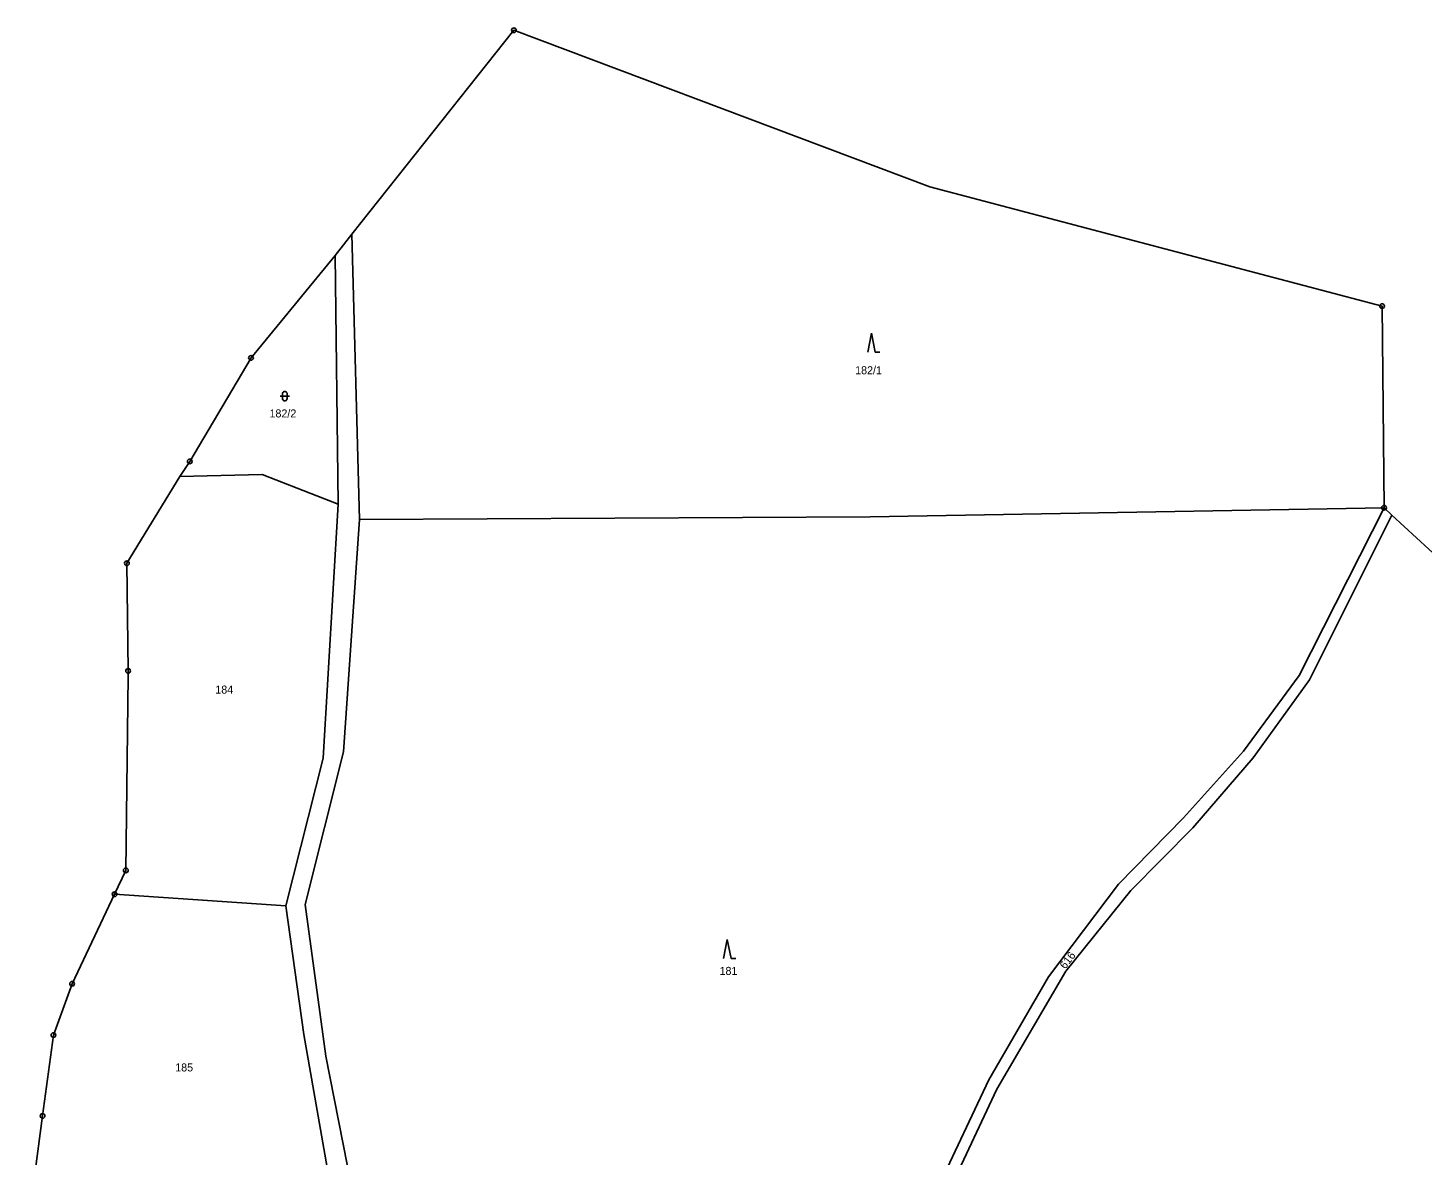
# Model space of a CAD drawing. Extents: x -794421 to -792735, y -1117671 to -1115559.
# Drawn here: x -793544 to -793247.9, y -1115798.8 to -1115559.5 of the extents above; entities that cross this region are included whole.
import ezdxf

# ---------------------------------------------------------------- set-up
doc = ezdxf.new("R2010")
doc.units = 0
for name, color, linetype in [('Vrstva 1', 7, 'Continuous'), ('Vrstva 14', 7, 'Continuous'), ('Vrstva 23', 7, 'Continuous'), ('Vrstva 28', 7, 'Continuous'), ('Vrstva 3', 7, 'Continuous')]:
    doc.layers.add(name, color=color, linetype=linetype)

msp = doc.modelspace()

# ---------------------------------------------------------------- linework, layer by layer
at = {"layer": 'Vrstva 1'}
for p, q in [((-793475.17, -1115603.32), (-793473.53, -1115663.84)), ((-793478.72, -1115607.79), (-793478.08, -1115660.64)), ((-793511.69, -1115654.77), (-793494.18, -1115654.33)), ((-793494.18, -1115654.33), (-793478.08, -1115660.64)), ((-793478.08, -1115660.64), (-793481.27, -1115714.55)), ((-793365.11, -1115663.31), (-793255.97, -1115661.39)), ((-793255.97, -1115661.39), (-793273.99, -1115696.97)), ((-793473.53, -1115663.84), (-793476.92, -1115713.19)), ((-793473.53, -1115663.84), (-793365.11, -1115663.31)), ((-793271.79, -1115697.9), (-793254.28, -1115662.95)), ((-793273.99, -1115696.97), (-793285.84, -1115713.04)), ((-793271.79, -1115697.9), (-793283.72, -1115714.46)), ((-793481.27, -1115714.55), (-793489.16, -1115745.93)), ((-793476.92, -1115713.19), (-793485.04, -1115745.64)), ((-793285.84, -1115713.04), (-793298.55, -1115727.22)), ((-793283.72, -1115714.46), (-793296.6, -1115729.31)), ((-793298.55, -1115727.22), (-793312.33, -1115741.27)), ((-793296.6, -1115729.31), (-793309.74, -1115742.61)), ((-793312.33, -1115741.27), (-793327.22, -1115760.95)), ((-793525.55, -1115743.43), (-793489.16, -1115745.93)), ((-793309.74, -1115742.61), (-793323.54, -1115759.78)), ((-793489.16, -1115745.93), (-793485.36, -1115773.22)), ((-793485.04, -1115745.64), (-793480.65, -1115777.84)), ((-793327.22, -1115760.95), (-793339.86, -1115782.82)), ((-793323.54, -1115759.78), (-793338.19, -1115784.82)), ((-793485.36, -1115773.22), (-793478.09, -1115814.58)), ((-793480.65, -1115777.84), (-793473.46, -1115814.55)), ((-793339.86, -1115782.82), (-793359.82, -1115825.02)), ((-793338.19, -1115784.82), (-793357.42, -1115825.77))]:
    msp.add_line(p, q, dxfattribs=at)
at = {"layer": 'Vrstva 23'}
for p, q in [((-793365.61, -1115628.34), (-793364.81, -1115624.34)), ((-793364.81, -1115624.34), (-793364.01, -1115628.34)), ((-793364.01, -1115628.34), (-793363.01, -1115628.34)), ((-793490.4, -1115637.68), (-793488.4, -1115637.68)), ((-793489.9, -1115637.08), (-793489.8, -1115636.88)), ((-793489.9, -1115638.28), (-793489.9, -1115637.08)), ((-793489.8, -1115636.88), (-793489.7, -1115636.78)), ((-793489.7, -1115636.78), (-793489.5, -1115636.68)), ((-793489.5, -1115636.68), (-793489.3, -1115636.68)), ((-793489.3, -1115636.68), (-793489.1, -1115636.78)), ((-793489.1, -1115636.78), (-793489, -1115636.88)), ((-793489, -1115636.88), (-793488.9, -1115637.08)), ((-793488.9, -1115637.08), (-793488.9, -1115638.28)), ((-793489.8, -1115638.48), (-793489.9, -1115638.28)), ((-793489.7, -1115638.58), (-793489.8, -1115638.48)), ((-793489.5, -1115638.68), (-793489.7, -1115638.58)), ((-793489.3, -1115638.68), (-793489.5, -1115638.68)), ((-793489.1, -1115638.58), (-793489.3, -1115638.68)), ((-793489, -1115638.48), (-793489.1, -1115638.58)), ((-793488.9, -1115638.28), (-793489, -1115638.48)), ((-793396.23, -1115757.06), (-793395.43, -1115753.06)), ((-793395.43, -1115753.06), (-793394.63, -1115757.06)), ((-793394.63, -1115757.06), (-793393.63, -1115757.06))]:
    msp.add_line(p, q, dxfattribs=at)
at = {"layer": 'Vrstva 28'}
for centre, radius in [((-793440.73, -1115559.99), 0.5), ((-793440.73, -1115559.99), 0.01), ((-793256.39, -1115618.57), 0.5), ((-793256.39, -1115618.57), 0.01), ((-793496.57, -1115629.57), 0.5), ((-793496.57, -1115629.57), 0.01), ((-793509.58, -1115651.54), 0.5), ((-793509.58, -1115651.54), 0.01), ((-793255.97, -1115661.39), 0.5), ((-793255.97, -1115661.39), 0.01), ((-793522.92, -1115673.15), 0.5), ((-793522.92, -1115673.15), 0.01), ((-793522.66, -1115696.03), 0.5), ((-793522.66, -1115696.03), 0.01), ((-793523.15, -1115738.36), 0.5), ((-793523.15, -1115738.36), 0.01), ((-793525.55, -1115743.43), 0.5), ((-793525.55, -1115743.43), 0.01), ((-793534.56, -1115762.43), 0.5), ((-793534.56, -1115762.43), 0.01), ((-793538.54, -1115773.34), 0.5), ((-793538.54, -1115773.34), 0.01), ((-793540.84, -1115790.5), 0.5), ((-793540.84, -1115790.5), 0.01)]:
    msp.add_circle(centre, radius, dxfattribs=at)
at = {"layer": 'Vrstva 3'}
for p, q in [((-793440.73, -1115559.99), (-793475.17, -1115603.32)), ((-793352.39, -1115593.24), (-793440.73, -1115559.99)), ((-793256.39, -1115618.57), (-793352.39, -1115593.24)), ((-793475.17, -1115603.32), (-793478.72, -1115607.79)), ((-793478.72, -1115607.79), (-793496.57, -1115629.57)), ((-793255.97, -1115661.39), (-793256.39, -1115618.57)), ((-793496.57, -1115629.57), (-793509.58, -1115651.54)), ((-793509.58, -1115651.54), (-793511.69, -1115654.77)), ((-793511.69, -1115654.77), (-793522.92, -1115673.15)), ((-793254.28, -1115662.95), (-793255.97, -1115661.39)), ((-793225.47, -1115689.52), (-793254.28, -1115662.95)), ((-793522.92, -1115673.15), (-793522.66, -1115696.03)), ((-793522.64, -1115697.15), (-793523.15, -1115738.36)), ((-793522.66, -1115696.03), (-793522.64, -1115697.15)), ((-793523.15, -1115738.36), (-793525.55, -1115743.43)), ((-793525.55, -1115743.43), (-793534.56, -1115762.43)), ((-793534.56, -1115762.43), (-793538.54, -1115773.34)), ((-793538.54, -1115773.34), (-793540.84, -1115790.5)), ((-793540.84, -1115790.5), (-793543.95, -1115813.52))]:
    msp.add_line(p, q, dxfattribs=at)

# ---------------------------------------------------------------- texts
at = {"layer": 'Vrstva 14'}
for s, p in [('182/1', (-793368.276, -1115633.03)), ('182/2', (-793492.643, -1115642.2)), ('184', (-793504.146, -1115700.83)), ('181', (-793397.073, -1115760.56)), ('185', (-793512.666, -1115781.06))]:
    msp.add_text(s, height=1.7, dxfattribs=at).set_placement(p)
msp.add_text('616', height=1.7, rotation=52.62939, dxfattribs=at).set_placement((-793323.658, -1115759.451))

doc.saveas('drawing.dxf')
